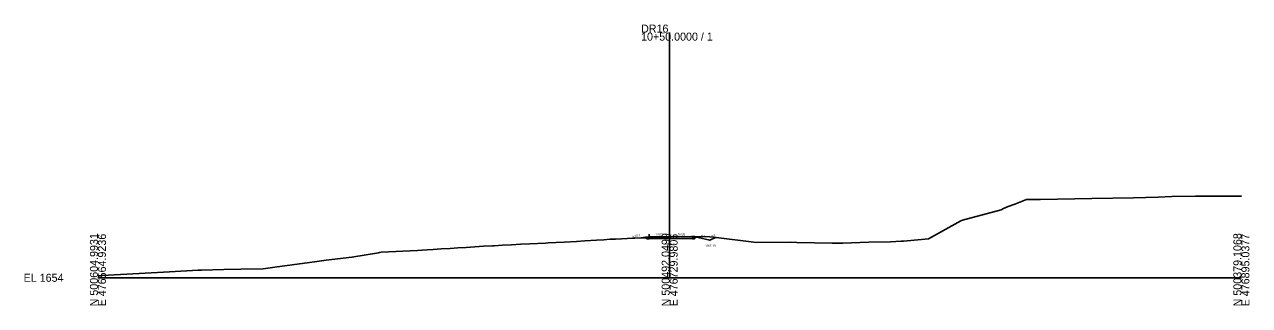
# Model space of a CAD drawing. Extents: x -26 to 403, y -10 to 1535.
# Drawn here: x -25.7 to 402.8, y 490.3 to 588.6 of the extents above; entities that cross this region are included whole.
import ezdxf

# ---------------------------------------------------------------- set-up
doc = ezdxf.new("R2010")
doc.units = 0
for name, color, linetype in [('Exist Cross Section Cell', 7, 'Continuous'), ('Exist XS Center Line Elevation Label', 7, 'Continuous'), ('Exist XS Ground Line', 7, 'Continuous'), ('Prop XS Ditch Slope Text', 7, 'Continuous'), ('Prop XS Ditch Standard Text', 7, 'Continuous'), ('Prop XS Earthwork Shape', 7, 'Continuous'), ('Prop XS EOT Tick Mark', 7, 'Continuous'), ('Prop XS Finish Grade', 7, 'Continuous'), ('Prop XS Finish Grade Earthwork', 7, 'Continuous'), ('Prop XS Finish Grade Pavement', 7, 'Continuous'), ('Prop XS Pvmt Edge Slope', 7, 'Continuous'), ('Prop XS SE Text', 7, 'Continuous'), ('Prop XS Shoulder Borrow Shape', 7, 'Continuous'), ('Prop XS Side Slope Text', 7, 'Continuous'), ('Prop XS Subgrade Earthwork', 7, 'Continuous')]:
    doc.layers.add(name, color=color, linetype=linetype)

msp = doc.modelspace()

# ---------------------------------------------------------------- linework, layer by layer
at = {"layer": 'Exist Cross Section Cell'}
for p, q in [((200, 500), (200, 585.74)), ((0, 500), (200, 500)), ((200, 500), (400, 500))]:
    msp.add_line(p, q, dxfattribs=at)
at = {"layer": 'Exist XS Center Line Elevation Label'}
msp.add_line((153.7, 512), (153.7, 512), dxfattribs=at)
at = {"layer": 'Exist XS Ground Line'}
msp.add_lwpolyline([(0, 500.6), (0.2, 500.72), (1.33, 500.8), (14.39, 501.49), (25.07, 502.09), (35.05, 502.61), (36.28, 502.67), (44.06, 502.93), (49.94, 502.97), (57.74, 503.15), (61.86, 503.68), (73.96, 505.39), (75.78, 505.6), (79.85, 506.15), (88.84, 507.18), (98.14, 508.78), (98.47, 508.82), (99.08, 508.9), (111.77, 509.56), (113.44, 509.67), (115.22, 509.79), (117.3, 509.93), (120.03, 510.1), (123.19, 510.27), (125.9, 510.44), (128.82, 510.63), (131.86, 510.83), (134.93, 511.01), (138.01, 511.18), (138.58, 511.21), (141.53, 511.37), (144.62, 511.54), (147.87, 511.71), (151.06, 511.87), (156.56, 512.15), (157.54, 512.2), (163.07, 512.51), (167.46, 512.73), (170.31, 512.97), (174.36, 513.19), (176.99, 513.32), (179.2, 513.45), (181.1, 513.55), (187.27, 513.83), (187.78, 513.85), (191.9, 513.99), (192.72, 514.03), (200, 514.21), (207.63, 514.41), (208.14, 514.43), (208.76, 514.45), (214.06, 514.29), (215.37, 514.24), (230.43, 512.31), (242.31, 512.41), (244.53, 512.29), (256.85, 512.1), (258.23, 512.11), (260.58, 512.06), (269.71, 512.41), (277.28, 512.61), (280.99, 512.82), (281.75, 512.86), (288.05, 513.41), (290.59, 513.66), (300.8, 519.34), (301.88, 519.89), (302.45, 520.16), (316, 523.76), (316.82, 524.21), (318.41, 524.9), (320.69, 525.77), (324.83, 527.36), (329.69, 527.43), (347.7, 527.73), (362.31, 527.95), (370.92, 528.22), (375.62, 528.39), (383.97, 528.52), (388.07, 528.58), (388.67, 528.57), (389.66, 528.58), (397.51, 528.51), (399.13, 528.52), (400, 528.54)], dxfattribs=at)
at = {"layer": 'Prop XS Earthwork Shape'}
for points in [[(191.72, 513.99), (191.9, 513.99), (192.72, 514.03), (200, 514.21), (207.63, 514.41), (208.14, 514.43), (208.76, 514.45), (214.06, 514.29), (215.37, 514.24), (216.09, 514.14), (214, 513.1), (210, 514.1), (209.26, 514.16), (208.68, 513.58), (208, 513.59), (200, 513.75), (192.83, 513.61), (192.12, 513.6)], [(191.72, 513.99), (191.52, 514.18), (190.75, 514.12), (189.97, 513.93)]]:
    msp.add_lwpolyline(points, close=True, dxfattribs=at)
at = {"layer": 'Prop XS EOT Tick Mark'}
msp.add_line((192.83, 514.28), (192.83, 515.28), dxfattribs=at)
at = {"layer": 'Prop XS Finish Grade'}
for p, q in [((192.83, 514.28), (191.52, 514.18)), ((208, 514.26), (209.26, 514.16))]:
    msp.add_line(p, q, dxfattribs=at)
at = {"layer": 'Prop XS Finish Grade Earthwork'}
for p, q in [((190.75, 514.12), (189.97, 513.93)), ((191.52, 514.18), (190.75, 514.12)), ((209.26, 514.16), (210, 514.1)), ((210, 514.1), (214, 513.1)), ((214, 513.1), (216.09, 514.14))]:
    msp.add_line(p, q, dxfattribs=at)
at = {"layer": 'Prop XS Finish Grade Pavement'}
for p, q in [((192.83, 514.28), (200, 514.42)), ((200, 514.42), (208, 514.26))]:
    msp.add_line(p, q, dxfattribs=at)
at = {"layer": 'Prop XS Pvmt Edge Slope'}
for p, q in [((192.83, 514.28), (192.12, 513.6)), ((208, 514.26), (208.68, 513.58))]:
    msp.add_line(p, q, dxfattribs=at)
at = {"layer": 'Prop XS Shoulder Borrow Shape'}
for points in [[(192.83, 514.28), (192.12, 513.6), (191.52, 514.18)], [(208.68, 513.58), (209.26, 514.16), (208, 514.26)]]:
    msp.add_lwpolyline(points, close=True, dxfattribs=at)
at = {"layer": 'Prop XS Subgrade Earthwork'}
for p, q in [((192.12, 513.6), (191.52, 514.18)), ((192.83, 513.61), (192.12, 513.6)), ((200, 513.75), (192.83, 513.61)), ((208, 513.59), (200, 513.75)), ((208, 513.59), (208.68, 513.58)), ((208.68, 513.58), (209.26, 514.16))]:
    msp.add_line(p, q, dxfattribs=at)

# ---------------------------------------------------------------- texts
at = {"layer": 'Exist Cross Section Cell'}
for s, p in [('DR16', (190, 585.74)), ('10+50.0000 / 1', (190, 582.94)), ('EL 1654', (-26, 498.6))]:
    msp.add_text(s, height=2.8, dxfattribs=at).set_placement(p)
for s, p in [('N 500604.9931', (0, 490)), ('E 476564.9236', (2.8, 490)), ('N 500492.0499', (200, 490)), ('E 476729.9806', (202.8, 490)), ('N 500379.1068', (400, 490)), ('E 476895.0377', (402.8, 490))]:
    msp.add_text(s, height=2.8, rotation=90, dxfattribs=at).set_placement(p)
at = {"layer": 'Exist XS Center Line Elevation Label'}
msp.add_text('1668.21', height=0.75, dxfattribs=at).set_placement((198.4, 511.46))
at = {"layer": 'Prop XS Ditch Slope Text'}
for s, rotation, p in [('4.15:1', 13.5618, (186.93, 513.97)), ('4:1', 345.9638, (210.89, 514.49))]:
    msp.add_text(s, height=0.75, rotation=rotation, dxfattribs=at).set_placement(p)
at = {"layer": 'Prop XS Ditch Standard Text'}
msp.add_text('1667.10', height=0.75, dxfattribs=at).set_placement((212.3, 510.85))
at = {"layer": 'Prop XS SE Text'}
for rotation, p in [(1.1458, (195.23, 514.82)), (358.8542, (202.83, 514.87))]:
    msp.add_text('0.020', height=0.75, rotation=rotation, dxfattribs=at).set_placement(p)
at = {"layer": 'Prop XS Side Slope Text'}
msp.add_text('2:1', height=0.75, rotation=26.5651, dxfattribs=at).set_placement((214.8, 514.08))

doc.saveas('drawing.dxf')
